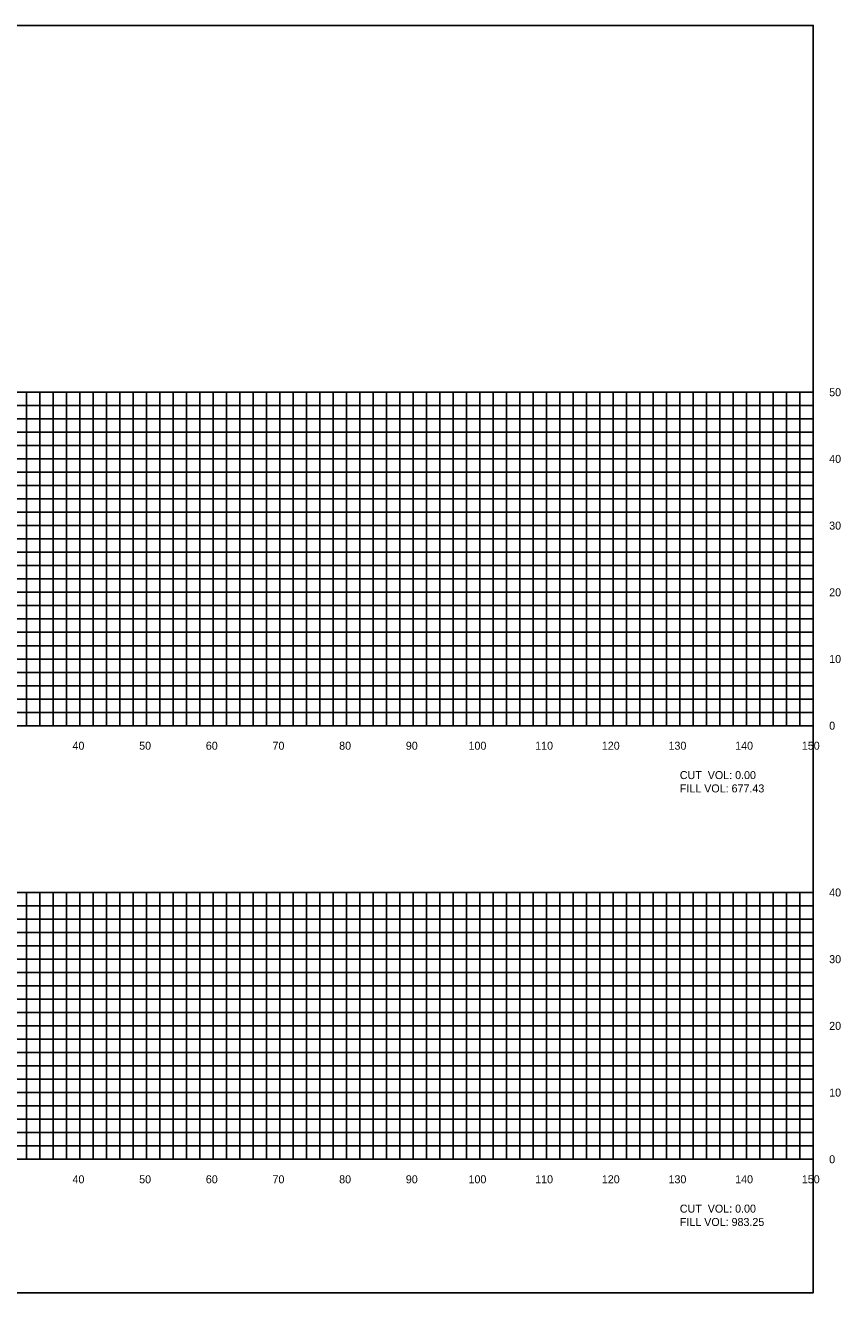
# Model space of a CAD drawing. Extents: x 1797518 to 1804843, y 248068 to 251132.
# Drawn here: x 1804022.8 to 1804145.1, y 250079.4 to 250269.4 of the extents above; entities that cross this region are included whole.
import ezdxf

# ---------------------------------------------------------------- set-up
doc = ezdxf.new("R2010")
doc.units = 0
for name, color, linetype in [('10', 7, 'Continuous'), ('31', 7, 'Continuous'), ('60', 7, 'Continuous'), ('ANNO-TXT', 7, 'Continuous'), ('Level 62', 7, 'Continuous')]:
    doc.layers.add(name, color=color, linetype=linetype)

msp = doc.modelspace()

# ---------------------------------------------------------------- linework, layer by layer
msp.add_lwpolyline([(1803841, 250079.43), (1804141, 250079.43), (1804141, 250269.43), (1803841, 250269.43)], close=True)
at = {"layer": '60'}
for p, q in [((1804141, 250164.43), (1804141, 250214.43)), ((1804141.06, 250214.43), (1804141, 250214.43)), ((1804141.06, 250204.43), (1804141, 250204.43)), ((1804141.06, 250194.43), (1804141, 250194.43)), ((1804141.06, 250184.43), (1804141, 250184.43)), ((1804141.06, 250174.43), (1804141, 250174.43)), ((1803841, 250164.43), (1804141, 250164.43)), ((1804031, 250164.37), (1804031, 250164.43)), ((1804041, 250164.37), (1804041, 250164.43)), ((1804051, 250164.37), (1804051, 250164.43)), ((1804061, 250164.37), (1804061, 250164.43)), ((1804071, 250164.37), (1804071, 250164.43)), ((1804081, 250164.37), (1804081, 250164.43)), ((1804091, 250164.37), (1804091, 250164.43)), ((1804101, 250164.37), (1804101, 250164.43)), ((1804111, 250164.37), (1804111, 250164.43)), ((1804121, 250164.37), (1804121, 250164.43)), ((1804131, 250164.37), (1804131, 250164.43)), ((1804141, 250164.37), (1804141, 250164.43)), ((1804141.06, 250164.43), (1804141, 250164.43)), ((1804141, 250099.43), (1804141, 250139.43)), ((1804141.06, 250139.43), (1804141, 250139.43)), ((1804141.06, 250129.43), (1804141, 250129.43)), ((1804141.06, 250119.43), (1804141, 250119.43)), ((1804141.06, 250109.43), (1804141, 250109.43)), ((1803841, 250099.43), (1804141, 250099.43)), ((1804031, 250099.37), (1804031, 250099.43)), ((1804041, 250099.37), (1804041, 250099.43)), ((1804051, 250099.37), (1804051, 250099.43)), ((1804061, 250099.37), (1804061, 250099.43)), ((1804071, 250099.37), (1804071, 250099.43)), ((1804081, 250099.37), (1804081, 250099.43)), ((1804091, 250099.37), (1804091, 250099.43)), ((1804101, 250099.37), (1804101, 250099.43)), ((1804111, 250099.37), (1804111, 250099.43)), ((1804121, 250099.37), (1804121, 250099.43)), ((1804131, 250099.37), (1804131, 250099.43)), ((1804141, 250099.37), (1804141, 250099.43)), ((1804141.06, 250099.43), (1804141, 250099.43))]:
    msp.add_line(p, q, dxfattribs=at)
at = {"layer": 'Level 62'}
for p, q in [((1803841, 250214.43), (1804141, 250214.43)), ((1804023, 250164.43), (1804023, 250214.43)), ((1804025, 250164.43), (1804025, 250214.43)), ((1804027, 250164.43), (1804027, 250214.43)), ((1804029, 250164.43), (1804029, 250214.43)), ((1804031, 250164.43), (1804031, 250214.43)), ((1804033, 250164.43), (1804033, 250214.43)), ((1804035, 250164.43), (1804035, 250214.43)), ((1804037, 250164.43), (1804037, 250214.43)), ((1804039, 250164.43), (1804039, 250214.43)), ((1804041, 250164.43), (1804041, 250214.43)), ((1804043, 250164.43), (1804043, 250214.43)), ((1804045, 250164.43), (1804045, 250214.43)), ((1804047, 250164.43), (1804047, 250214.43)), ((1804049, 250164.43), (1804049, 250214.43)), ((1804051, 250164.43), (1804051, 250214.43)), ((1804053, 250164.43), (1804053, 250214.43)), ((1804055, 250164.43), (1804055, 250214.43)), ((1804057, 250164.43), (1804057, 250214.43)), ((1804059, 250164.43), (1804059, 250214.43)), ((1804061, 250164.43), (1804061, 250214.43)), ((1804063, 250164.43), (1804063, 250214.43)), ((1804065, 250164.43), (1804065, 250214.43)), ((1804067, 250164.43), (1804067, 250214.43)), ((1804069, 250164.43), (1804069, 250214.43)), ((1804071, 250164.43), (1804071, 250214.43)), ((1804073, 250164.43), (1804073, 250214.43)), ((1804075, 250164.43), (1804075, 250214.43)), ((1804077, 250164.43), (1804077, 250214.43)), ((1804079, 250164.43), (1804079, 250214.43)), ((1804081, 250164.43), (1804081, 250214.43)), ((1804083, 250164.43), (1804083, 250214.43)), ((1804085, 250164.43), (1804085, 250214.43)), ((1804087, 250164.43), (1804087, 250214.43)), ((1804089, 250164.43), (1804089, 250214.43)), ((1804091, 250164.43), (1804091, 250214.43)), ((1804093, 250164.43), (1804093, 250214.43)), ((1804095, 250164.43), (1804095, 250214.43)), ((1804097, 250164.43), (1804097, 250214.43)), ((1804099, 250164.43), (1804099, 250214.43)), ((1804101, 250164.43), (1804101, 250214.43)), ((1804103, 250164.43), (1804103, 250214.43)), ((1804105, 250164.43), (1804105, 250214.43)), ((1804107, 250164.43), (1804107, 250214.43)), ((1804109, 250164.43), (1804109, 250214.43)), ((1804111, 250164.43), (1804111, 250214.43)), ((1804113, 250164.43), (1804113, 250214.43)), ((1804115, 250164.43), (1804115, 250214.43)), ((1804117, 250164.43), (1804117, 250214.43)), ((1804119, 250164.43), (1804119, 250214.43)), ((1804121, 250164.43), (1804121, 250214.43)), ((1804123, 250164.43), (1804123, 250214.43)), ((1804125, 250164.43), (1804125, 250214.43)), ((1804127, 250164.43), (1804127, 250214.43)), ((1804129, 250164.43), (1804129, 250214.43)), ((1804131, 250164.43), (1804131, 250214.43)), ((1804133, 250164.43), (1804133, 250214.43)), ((1804135, 250164.43), (1804135, 250214.43)), ((1804137, 250164.43), (1804137, 250214.43)), ((1804139, 250164.43), (1804139, 250214.43)), ((1804141, 250164.43), (1804141, 250214.43)), ((1803841, 250212.43), (1804141, 250212.43)), ((1803841, 250210.43), (1804141, 250210.43)), ((1803841, 250208.43), (1804141, 250208.43)), ((1803841, 250206.43), (1804141, 250206.43)), ((1803841, 250204.43), (1804141, 250204.43)), ((1803841, 250202.43), (1804141, 250202.43)), ((1803841, 250200.43), (1804141, 250200.43)), ((1803841, 250198.43), (1804141, 250198.43)), ((1803841, 250196.43), (1804141, 250196.43)), ((1803841, 250194.43), (1804141, 250194.43)), ((1803841, 250192.43), (1804141, 250192.43)), ((1803841, 250190.43), (1804141, 250190.43)), ((1803841, 250188.43), (1804141, 250188.43)), ((1803841, 250186.43), (1804141, 250186.43)), ((1803841, 250184.43), (1804141, 250184.43)), ((1803841, 250182.43), (1804141, 250182.43)), ((1803841, 250180.43), (1804141, 250180.43)), ((1803841, 250178.43), (1804141, 250178.43)), ((1803841, 250176.43), (1804141, 250176.43)), ((1803841, 250174.43), (1804141, 250174.43)), ((1803841, 250172.43), (1804141, 250172.43)), ((1803841, 250170.43), (1804141, 250170.43)), ((1803841, 250168.43), (1804141, 250168.43)), ((1803841, 250166.43), (1804141, 250166.43)), ((1803841, 250164.43), (1804141, 250164.43)), ((1803841, 250139.43), (1804141, 250139.43)), ((1804023, 250099.43), (1804023, 250139.43)), ((1804025, 250099.43), (1804025, 250139.43)), ((1804027, 250099.43), (1804027, 250139.43)), ((1804029, 250099.43), (1804029, 250139.43)), ((1804031, 250099.43), (1804031, 250139.43)), ((1804033, 250099.43), (1804033, 250139.43)), ((1804035, 250099.43), (1804035, 250139.43)), ((1804037, 250099.43), (1804037, 250139.43)), ((1804039, 250099.43), (1804039, 250139.43)), ((1804041, 250099.43), (1804041, 250139.43)), ((1804043, 250099.43), (1804043, 250139.43)), ((1804045, 250099.43), (1804045, 250139.43)), ((1804047, 250099.43), (1804047, 250139.43)), ((1804049, 250099.43), (1804049, 250139.43)), ((1804051, 250099.43), (1804051, 250139.43)), ((1804053, 250099.43), (1804053, 250139.43)), ((1804055, 250099.43), (1804055, 250139.43)), ((1804057, 250099.43), (1804057, 250139.43)), ((1804059, 250099.43), (1804059, 250139.43)), ((1804061, 250099.43), (1804061, 250139.43)), ((1804063, 250099.43), (1804063, 250139.43)), ((1804065, 250099.43), (1804065, 250139.43)), ((1804067, 250099.43), (1804067, 250139.43)), ((1804069, 250099.43), (1804069, 250139.43)), ((1804071, 250099.43), (1804071, 250139.43)), ((1804073, 250099.43), (1804073, 250139.43)), ((1804075, 250099.43), (1804075, 250139.43)), ((1804077, 250099.43), (1804077, 250139.43)), ((1804079, 250099.43), (1804079, 250139.43)), ((1804081, 250099.43), (1804081, 250139.43)), ((1804083, 250099.43), (1804083, 250139.43)), ((1804085, 250099.43), (1804085, 250139.43)), ((1804087, 250099.43), (1804087, 250139.43)), ((1804089, 250099.43), (1804089, 250139.43)), ((1804091, 250099.43), (1804091, 250139.43)), ((1804093, 250099.43), (1804093, 250139.43)), ((1804095, 250099.43), (1804095, 250139.43)), ((1804097, 250099.43), (1804097, 250139.43)), ((1804099, 250099.43), (1804099, 250139.43)), ((1804101, 250099.43), (1804101, 250139.43)), ((1804103, 250099.43), (1804103, 250139.43)), ((1804105, 250099.43), (1804105, 250139.43)), ((1804107, 250099.43), (1804107, 250139.43)), ((1804109, 250099.43), (1804109, 250139.43)), ((1804111, 250099.43), (1804111, 250139.43)), ((1804113, 250099.43), (1804113, 250139.43)), ((1804115, 250099.43), (1804115, 250139.43)), ((1804117, 250099.43), (1804117, 250139.43)), ((1804119, 250099.43), (1804119, 250139.43)), ((1804121, 250099.43), (1804121, 250139.43)), ((1804123, 250099.43), (1804123, 250139.43)), ((1804125, 250099.43), (1804125, 250139.43)), ((1804127, 250099.43), (1804127, 250139.43)), ((1804129, 250099.43), (1804129, 250139.43)), ((1804131, 250099.43), (1804131, 250139.43)), ((1804133, 250099.43), (1804133, 250139.43)), ((1804135, 250099.43), (1804135, 250139.43)), ((1804137, 250099.43), (1804137, 250139.43)), ((1804139, 250099.43), (1804139, 250139.43)), ((1804141, 250099.43), (1804141, 250139.43)), ((1803841, 250137.43), (1804141, 250137.43)), ((1803841, 250135.43), (1804141, 250135.43)), ((1803841, 250133.43), (1804141, 250133.43)), ((1803841, 250131.43), (1804141, 250131.43)), ((1803841, 250129.43), (1804141, 250129.43)), ((1803841, 250127.43), (1804141, 250127.43)), ((1803841, 250125.43), (1804141, 250125.43)), ((1803841, 250123.43), (1804141, 250123.43)), ((1803841, 250121.43), (1804141, 250121.43)), ((1803841, 250119.43), (1804141, 250119.43)), ((1803841, 250117.43), (1804141, 250117.43)), ((1803841, 250115.43), (1804141, 250115.43)), ((1803841, 250113.43), (1804141, 250113.43)), ((1803841, 250111.43), (1804141, 250111.43)), ((1803841, 250109.43), (1804141, 250109.43)), ((1803841, 250107.43), (1804141, 250107.43)), ((1803841, 250105.43), (1804141, 250105.43)), ((1803841, 250103.43), (1804141, 250103.43)), ((1803841, 250101.43), (1804141, 250101.43)), ((1803841, 250099.43), (1804141, 250099.43))]:
    msp.add_line(p, q, dxfattribs=at)

# ---------------------------------------------------------------- texts
at = {"layer": '10'}
for s, p in [('40', (1804029.9, 250160.83)), ('50', (1804039.9, 250160.83)), ('60', (1804049.9, 250160.83)), ('70', (1804059.9, 250160.83)), ('80', (1804069.9, 250160.83)), ('90', (1804079.9, 250160.83)), ('100', (1804089.3, 250160.83)), ('110', (1804099.3, 250160.83)), ('120', (1804109.3, 250160.83)), ('130', (1804119.3, 250160.83)), ('140', (1804129.3, 250160.83)), ('150', (1804139.3, 250160.83)), ('40', (1804029.9, 250095.83)), ('50', (1804039.9, 250095.83)), ('60', (1804049.9, 250095.83)), ('70', (1804059.9, 250095.83)), ('80', (1804069.9, 250095.83)), ('90', (1804079.9, 250095.83)), ('100', (1804089.3, 250095.83)), ('110', (1804099.3, 250095.83)), ('120', (1804109.3, 250095.83)), ('130', (1804119.3, 250095.83)), ('140', (1804129.3, 250095.83)), ('150', (1804139.3, 250095.83))]:
    msp.add_text(s, height=1.2, dxfattribs=at).set_placement(p)
at = {"layer": '31'}
for s, p in [('50', (1804143.4, 250213.83)), ('40', (1804143.4, 250203.83)), ('30', (1804143.4, 250193.83)), ('20', (1804143.4, 250183.83)), ('10', (1804143.4, 250173.83)), ('0', (1804143.4, 250163.83)), ('40', (1804143.4, 250138.83)), ('30', (1804143.4, 250128.83)), ('20', (1804143.4, 250118.83)), ('10', (1804143.4, 250108.83)), ('0', (1804143.4, 250098.83))]:
    msp.add_text(s, height=1.2, dxfattribs=at).set_placement(p)
at = {"layer": 'ANNO-TXT'}
for s, p in [('CUT  VOL: 0.00', (1804121, 250156.43)), ('FILL VOL: 677.43', (1804121, 250154.43)), ('CUT  VOL: 0.00', (1804121, 250091.43)), ('FILL VOL: 983.25', (1804121, 250089.43))]:
    msp.add_text(s, height=1.2, dxfattribs=at).set_placement(p)

doc.saveas('drawing.dxf')
